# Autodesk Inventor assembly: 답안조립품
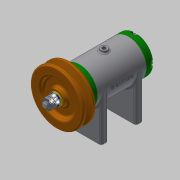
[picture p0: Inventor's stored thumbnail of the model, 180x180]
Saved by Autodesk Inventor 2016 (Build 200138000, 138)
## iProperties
Created: 2020-07
Part Number: 답안조립품
Document SubType Name: Assembly
Designer: user
Author: user
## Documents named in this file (15)
- C:\Users\user\Desktop\700706V1003\답안조립품.iam
- C:\Users\user\Desktop\700706V1003\본체.ipt
- C:\Users\user\Desktop\700706V1003\뒤커버.ipt
- C:\Users\user\Desktop\700706V1003\앞커버.ipt
- C:\Users\user\Desktop\700706V1003\축.ipt
- C:\Users\user\Desktop\700706V1003\키 3x3x12.ipt
- C:\Users\user\Desktop\700706V1003\베어링 6002.ipt
- C:\Users\user\Desktop\700706V1003\오일 실 15 25 7.ipt
- C:\Users\user\Desktop\700706V1003\볼트 M4x12.ipt
- C:\Users\user\Desktop\700706V1003\와셔 6x11.5.ipt
- C:\Users\user\Desktop\700706V1003\볼트 M6x8.ipt
- C:\Users\user\Desktop\700706V1003\V벨트풀리.ipt
- C:\Users\user\Desktop\700706V1003\와셔 8x17.ipt
- C:\Users\user\Desktop\700706V1003\스프링와셔 8.ipt
- C:\Users\user\Desktop\700706V1003\너트 M8.ipt
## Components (1 placed, 1 different names)
1. V벨트풀리:1 — 플러쉬:1
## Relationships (1: Flush 1)
- 플러쉬:1 [Flush]: V벨트풀리:1
